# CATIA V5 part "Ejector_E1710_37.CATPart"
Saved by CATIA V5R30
Part number: Vyhazovac_7x160_13
Nomenclature: E1710/7x160
Description: MEUSBURGER
Property "Material": "1.221"
Publications: "__DrillHole", "Base"
Bounding box of the stored display mesh (mm): x -5.992 to 5.992, y -5.992 to 5.992, z 0 to 151
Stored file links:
  E:\Bakalarka\Model\Forma_v7\Ejector_E1710_37.CATPart
  E:\dev\MoldDesign\intel_a\startup\components\MoldCatalog\Ejector\Meusburger\Ejector_E1710\TableE1710.txt
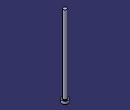
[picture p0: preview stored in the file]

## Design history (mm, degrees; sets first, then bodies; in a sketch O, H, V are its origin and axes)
Parameters
  Ref = "E1710/7x160" {design table}
  D1 = 7 mm {design table}
  D3 = 12 mm {design table}
  L = 160 mm {design table}
  L3 = 5 mm {design table}
  R = 0.5 mm {design table}
  k_d3 = 13 mm {design table}
  k_d1 = 7.2 mm {design table}
  k_F = 0.5 mm {design table}
  kl = 17 mm {design table}
  Mat = "1.221" {design table}
  HeatTreat = "ISO6751" {design table}
  Offset_Parting = 10 mm
  Anti_Rotation = "Normal"
  Anti_Rotation_D = 4 mm
  Anti_Rotation_D_Icut = 4 mm
  Add_Length_L = 1.3377 mm
  Add_Length_D3 = 0 mm
  SupplierRef = "Meusburger 2017"
  BmpRef = "F_MldEjectorD1"
  DrillHole_Length = 225 mm
  ValidationTest = false
  Anti_Rotation_D_min = 4 mm {= OffSet_D1 /2}
  Anti_Rotation_D_max = 5.925 mm {= D3/2-0.075mm}
  Anti_Rotation_D_ref = 4 mm {= Anti_Rotation_D}
  Anti_Rotation_D_Icut_ref = 4 mm {= Anti_Rotation_D_Icut}
  Anti_Rotation_Ref_Icut = 2.3246 mm
  Offset_L = 20 mm
  D = 7 mm {= D1}
  OffSet_D1 = 8 mm {= D1+2*R}
  OffSet_D3 = 13 mm {= D3+1mm}
  XG_Split = 54.5 mm
  YG_Split = -33 mm
  ZG_Split = -198 mm
  DirX_Split = 0 mm
  DirY_Split = 0 mm
  DirZ_Split = 1 mm
Set1 "BaseBody"
  Point1 "Base": (0, 0, 0)
  Plane1: type Offset, RefPlane xy-plane, Offset 225 {= DrillHole_Length}, reversed
  Sketch1 "Sketch.2" on xy-plane, origin (0, 0, 0), H (1, 0, 0), V (0, 1, 0)
    point P1 (-0.46, 1.1623)
    point P2 (0.46, 1.1623)
    construction line L1 (-0.46, 1.1623) -> (0.46, 1.1623)
    point P3 (0.46, -1.1623)
    line L2 (0.46, -1.1623) -> (0.46, 1.1623)
    point P4 (-0.46, -1.1623)
    construction line L3 (0.46, -1.1623) -> (-0.46, -1.1623)
    line L4 (-0.46, 1.1623) -> (-0.46, -1.1623)
    point P5 (-0.21, 1.1623)
    arc A1 centre (-0.21, 1.1623) radius 0.25 from (-0.21, 1.4123) to (-0.46, 1.1623) ccw
    point P7 (0.21, 1.1623)
    point P8 (0.21, 1.4123)
    arc A2 centre (0.21, 1.1623) radius 0.25 from (0.46, 1.1623) to (0.21, 1.4123) ccw
    line L5 (-0.21, 1.4123) -> (0.21, 1.4123)
    point P9 (-0.46, -1.1623)
    arc A3 centre (-0.21, -1.1623) radius 0.25 from (-0.46, -1.1623) to (-0.21, -1.4123) ccw
    point P11 (0.21, -1.4123)
    line L6 (-0.21, -1.4123) -> (0.21, -1.4123)
    point P12 (0.46, -1.1623)
    arc A4 centre (0.21, -1.1623) radius 0.25 from (0.21, -1.4123) to (0.46, -1.1623) ccw
    point P14 (-0.46, 1.1623)
    point P15 (-0.46, -1.1623)
    point P16 (0.46, 1.1623)
    point P17 (0.46, -1.1623)
    reference projected circle E1 centre (0, 0) radius 1.25 from edge [face of Shaft1 from Sketch2.L3 | face of Shaft1 from Sketch2.L4]
    reference projected circle E2 centre (0, 0) radius 1.25 from edge [face of Shaft1 from Sketch2.L3 | face of Shaft1 from Sketch2.L4]
    reference projected circle E3 centre (0, 0) radius 1.25 from edge [face of Shaft1 from Sketch2.L3 | face of Shaft1 from Sketch2.L4]
    reference projected circle E4 centre (0, 0) radius 1.25 from edge [face of Shaft1 from Sketch2.L3 | face of Shaft1 from Sketch2.L4]
    point P18 (-0.46, -1.1623)
    point P19 (-0.21, -1.4123)
    point P20 (0.21, -1.4123)
    point P21 (0.46, -1.1623)
    point P22 (-0.21, -1.4123)
    point P23 (0.21, -1.4123)
    distance P14 P15 = 2.3246 (reference)
    distance P16 P17 = 2.3246 (reference)
    distance L1 P14 = 0 (reference)
    radius A1 = 3.5
    distance L4 V = 4.01
    distance L2 V = 5.935
    distance L5 L6 = 12
    horizontal: L1 H, L3 H, L5 H
    vertical: L2 V, L4 V
    coincidence: P5 L1, P7 L1, P3 P12, P14 L4, P15 L4, P16 L2, P17 L2, P14 E1, P15 E2, P16 E3, P17 E4, P3 P21, P4 P18, P20 P23, P19 P22
    tangency: A1 L4, A2 L2, A2 L5, A1 L5
    symmetry: P1 P9 H, A1 A3 H, P8 P11 H, L5 L6 H, P2 P12 H, A2 A4 H
  DatumSurface1
Body1 "PartBody" (main body)
  Sketch2 "Sketch.1" on zx-plane, origin (0, 0, 0), H (-1, 0, 0), V (0, 0, 1)
    point P1 (0, 160)
    line L1 (3.5, 160) -> (0, 160)
    line L2 (3.5, 5) -> (3.5, 160)
    line L3 (6, 5) -> (3.5, 5)
    line L4 (6, 0) -> (6, 5)
    point P5 (0, 0)
    line L5 (0, 0) -> (6, 0)
    point P6 (0, 160)
    axis line L6 (0, 160) -> (0, 0)
    point P7 (0, 0)
    point P8 (3.5, 5)
    point P9 (3.5, 5)
    line L7 (0, 160) -> (0, 0)
    distance L5 L3 = 5 {= L3}
    distance L5 L1 = 160 {= L}
    distance L2 L6 = 3.5 {= D1 /2}
    distance L4 L6 = 6 {= D3 /2}
    coincidence: L6 P5, P1 L6, L5 H, L6 V, P7 O, P6 P1, P8 P9
    vertical: L2 V, L7 V
    horizontal: L1 H
  Shaft1 "Shaft.1": profile Sketch2, axis Sketch2.L6, angle 360
  Pocket1 "Pocket.1": profile Sketch1, direction (0, 0, 1), length 6, outer side, deactivated
  Pocket2 "Pocket.2": profile Sketch1, direction (0, 0, 1), length 6, outer side, deactivated
  Fillet1: radius 0.5 {= R}, on edge [face of Shaft1 from Sketch2.L2 | face of Shaft1 from Sketch2.L3]
  Pocket3: profile face of Shaft1 from Sketch2.L1, direction along face of Shaft1 from Sketch2.L1 reversed, up to face of DatumSurface1
Body2 "__DrillHole"
  Sketch3 "Sketch.3" on face of Shaft1, origin (0, 0, 0), H (1, 0, 0), V (0, -1, 0)
    point P1 (0, 0)
    reference projected point E1 (0, 0) from Point1
    coincidence: E1 P1
  Hole1 "Hole.1": placed by Sketch3, at (0, 0, 0) direction (0, 0, 1), diameter 8 {= OffSet_D1}, depth 140 {= L-Offset_L}
  Sketch4 "Sketch.4" on face of Shaft1, origin (0, 0, 0), H (1, 0, 0), V (0, -1, 0)
    point P1 (0, 0)
    reference projected point E1 (0, 0) from Point1
    coincidence: E1 P1
  Hole2 "Hole.2": placed by Sketch4, at (0, 0, 0) direction (0, 0, 1), diameter 7 {= D1}, depth 160 {= L}
  Sketch5 "Sketch.5" on face of Shaft1 from Sketch2.L3, origin (0, 0, 5), H (1, 0, 0), V (0, 1, 0)
    point P1 (0, 0)
    reference projected point E1 (0, 0) from Point1
    coincidence: E1 P1
  Hole3 "Hole.3": placed by Sketch5, at (0, 0, 5) direction (0, 0, -1), diameter 13 {= OffSet_D3}, depth 230 {= L3 +DrillHole_Length}
  Chamfer1: length 0.5 {= k_F}, angle 45, on edge [face of Hole1 | face of Hole3]
  Body3 "__Body.1"
    Pocket4 "Pocket.3": profile Sketch1, direction (0, 0, -1), length 225, opposite side length 5, deactivated
  Assemble1: tool Body3
  Chamfer2: length 0.5 {= k_F}, angle 45, on edge [start face of Pocket4 | face of Hole1], deactivated
  Body4 "__Body.2"
    Pocket5 "Pocket.4": profile Sketch1, direction (0, 0, -1), length 225, opposite side length 5, deactivated
  Assemble2: tool Body4
  Chamfer3: length 0.5 {= k_F}, angle 45, on edge [start face of Pocket5 | face of Hole1], deactivated
Relations
  design table "TableE1710", configuration 278, drives Ref, D1, D3, L, L3, R, k_d3, k_d1, k_F, kl, Mat, HeatTreat
  Offset_L = 20mm (deactivated)
  rule "Cut_Head_rule":
    let sketch_cut (length)
    let PartBody_Pocket_Sketch (Boolean)
    let I_PartBody_Pocket (Boolean)
    let D_PartBody_Pocket (Boolean)
    let N_DrillHole_Hole (Boolean)
    let N_DrillHole_Hole_Sketch (Boolean)
    let I_DrillHole_Pocket (Boolean)
    let D_DrillHole_Pocket (Boolean)
    /* --------------------------------------------------------------------------------------*/
    if Anti_Rotation =="Normal"
    {
    	sketch_cut=Anti_Rotation_D_max
    	PartBody_Pocket_Sketch = false
    	I_PartBody_Pocket = false
    	D_PartBody_Pocket = false
    	N_DrillHole_Hole = true
    	N_DrillHole_Hole_Sketch = true
    	I_DrillHole_Pocket = false
    	D_DrillHole_Pocket = false
    	Chamfer1.Activity= true
    	Chamfer2.Activity= false
    	Chamfer3.Activity= false
    }
    if Anti_Rotation == "I_Cut"
    {
    	sketch_cut=Anti_Rotation_D_Icut_ref
    	PartBody_Pocket_Sketch = true
    	I_PartBody_Pocket = true
    	D_PartBody_Pocket = false
    	N_DrillHole_Hole = false
    	N_DrillHole_Hole_Sketch = false
    	I_DrillHole_Pocket = true
    	D_DrillHole_Pocket = false
    	Chamfer1.Activity= false
    	Chamfer2.Activity= true
    	Chamfer3.Activity= false
    }
    if Anti_Rotation =="D_Cut"
    {
    	sketch_cut=Anti_Rotation_D_max
    	PartBody_Pocket_Sketch = true
    	I_PartBody_Pocket = false
    	D_PartBody_Pocket = true
    	N_DrillHole_Hole = false
    	N_DrillHole_Hole_Sketch = false
    	I_DrillHole_Pocket = false
    	D_DrillHole_Pocket = true
    	Chamfer1.Activity= false
    	Chamfer2.Activity= false
    	Chamfer3.Activity= true
    }
    /* --------------------------------------------------------------------------------------*/
    Sketch1.distance(L2 V) = sketch_cut+0.01mm
    Sketch1.distance(L4 V) =Anti_Rotation_D_ref+0.01mm
    Sketch1.radius(A1) =D/2
    Pocket4.FirstLimit.Depth = DrillHole_Length
    Pocket5.FirstLimit.Depth = DrillHole_Length
    Pocket1.FirstLimit.Depth = L3+1mm
    Pocket2.FirstLimit.Depth = L3+1mm
    Pocket4.SecondLimit.Depth = L3
    Pocket5.SecondLimit.Depth =L3
    Pocket1.Activity = I_PartBody_Pocket
    Pocket2.Activity = D_PartBody_Pocket
    Sketch1.Activity =PartBody_Pocket_Sketch
    Hole3.Activity= N_DrillHole_Hole
    Sketch5.Activity = N_DrillHole_Hole_Sketch
    Pocket4.Activity = I_DrillHole_Pocket
    Pocket5.Activity  = D_DrillHole_Pocket
  rule "Anti_Rotation_Icut_constrain":
    let Ref1(length)
    let Ref2(length)
    let Ref3(length)
    let Diam1(length)
    let Diam2(length)
    let Add_Length_Lmin (length)
    Ref1=Sketch1.distance(P14 P15)
    Ref2=Sketch1.distance(P16 P17)
    Diam1=D
    Diam2=D3
    /* --------------------------------------------------------------------*/
    if Ref1 >Ref2
    	Anti_Rotation_Ref_Icut = Ref1
    else
    	Anti_Rotation_Ref_Icut  =Ref2
    Add_Length_D3 .InferiorRange=Anti_Rotation_Ref_Icut /2+Diam1/2 -Diam2/2
    if Add_Length_D3 .InferiorRange<0mm
    	Add_Length_D3 .InferiorRange=0mm
    if ValidationTest == "true"
    	Ref3   = 2*Add_Length_L +Anti_Rotation_Ref_Icut  +2*Diam1/2
    else
    	Ref3  =Diam2+2*Add_Length_D3
    if Ref3 <Diam2
    {
    	Ref3 =Diam2
    }
    /* --------------------------------------------------------------------*/
    Sketch1.distance(L5 L6) = Ref3
    Add_Length_L .InferiorRange=Diam2/2-Anti_Rotation_Ref_Icut/2-Diam1/2
    Add_Length_Lmin=Diam2/2-Anti_Rotation_Ref_Icut/2-Diam1/2
    if Add_Length_Lmin<0mm
    	Add_Length_L .InferiorRange=0mm
    else
    	Add_Length_L .InferiorRange=Add_Length_Lmin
